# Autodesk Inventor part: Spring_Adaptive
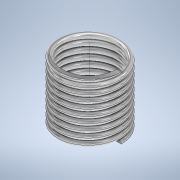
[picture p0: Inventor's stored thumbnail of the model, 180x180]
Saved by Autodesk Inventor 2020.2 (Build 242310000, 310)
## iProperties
Created: 2020-01
Part Number: Spring_Adaptive
Material: Nickel-Copper Alloy 400
Document SubType Name: Modeling
Designer: thira
Density: 8.83 g/cm^3
Appearance: Chrome - Polished
Author: thira
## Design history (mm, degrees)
sketch "Sketch1"
  geometry: C1 r 100 at (0, 0); 1 further point
  constraints: 1 centre point, 1 coincident
  dimensions: "d0" = 200 diameter of C1
extrude "Extrusion1" new body sketch "Sketch1" taper "d2" = 0 deg; distance "Height" = 200
sketch "Sketch2"
  geometry: L1 (100, 200)-(100, 0) reference; L2 (100, 0)-(-100, 0) reference; L3 (-100, 0)-(-100, 200) reference; L4 (-100, 200)-(100, 200) reference; L5 (100, 0)-(-100, 0) reference; C1 r 7.5 at (92.5, 0); 1 further point
  constraints: 1 centre point, 1 point on line, 1 tangent
  dimensions: "d3" = 15 diameter of C1
coil "Coil1" sketch "Sketch2" pitch "d4" = 20 (= 0.1 x Height); turns "d6" = 1; dims "d5" = 200 (= Height), "d7" = 0, angle "d8" = 90 deg, angle "d9" = 90 deg, "d10" = 0, "d11" = 0
body "Solid1"
node "Project Cut Edges1"
